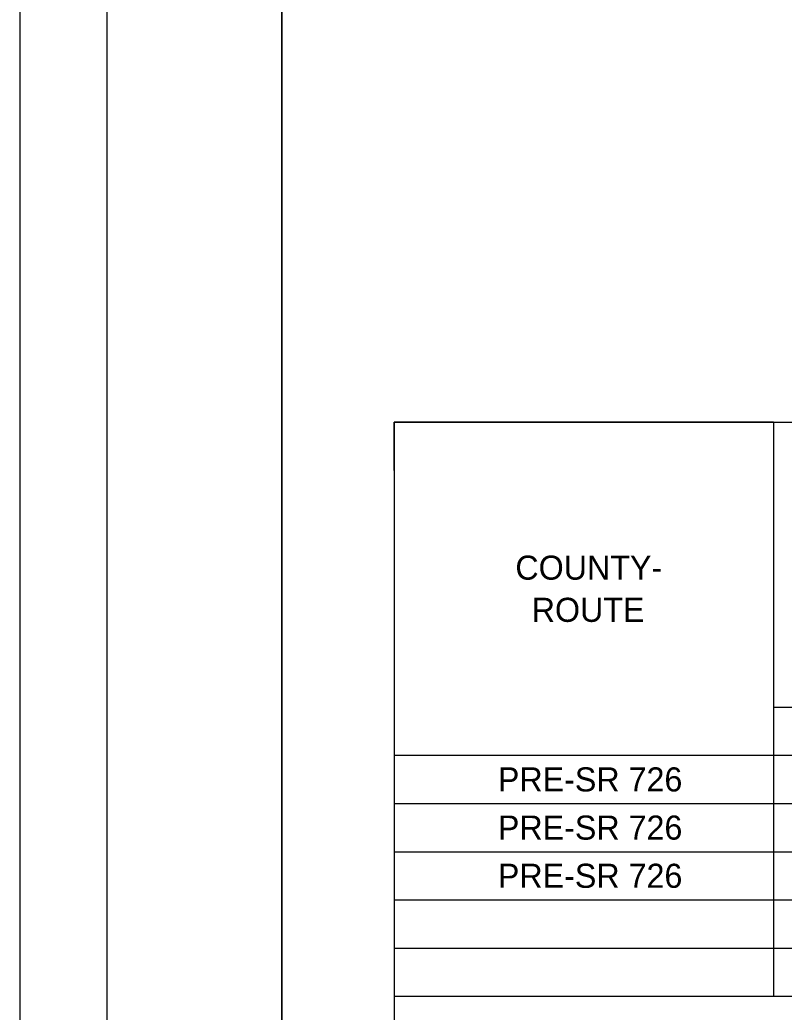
# Model space of a CAD drawing. Extents: x 0 to 34, y 0 to 22.
# Drawn here: x 0 to 4.38, y 3.42 to 9.11 of the extents above; entities that cross this region are included whole.
import ezdxf

# ---------------------------------------------------------------- set-up
doc = ezdxf.new("R2010")
doc.units = 0
for name, color, linetype in [('SH_Border', 7, 'Continuous'), ('SH_Cut_Line', 7, 'Continuous'), ('SH_Text', 7, 'Continuous')]:
    doc.layers.add(name, color=color, linetype=linetype)

msp = doc.modelspace()

# ---------------------------------------------------------------- linework, layer by layer
at = {"layer": 'SH_Border'}
for points in [[(0.5, 21.5), (1.5, 21.5), (1.5, 0.5), (0.5, 0.5)], [(1.5, 21.5), (33.5, 21.5), (33.5, 0.5), (1.5, 0.5)]]:
    msp.add_lwpolyline(points, close=True, dxfattribs=at)
at = {"layer": 'SH_Cut_Line'}
msp.add_lwpolyline([(0, 0), (34, 0), (34, 22), (0, 22)], close=True, dxfattribs=at)
at = {"layer": 'SH_Text'}
for p, q in [((2.1442, 6.801), (5.3482, 6.801)), ((2.1442, 6.801), (2.1442, 5.997)), ((4.3162, 6.801), (4.3162, 5.997)), ((2.1442, 5.997), (2.1442, 5.169)), ((4.3162, 5.997), (4.3162, 5.169)), ((2.1442, 5.169), (2.1442, 4.065)), ((4.3162, 5.169), (5.3482, 5.169)), ((4.3162, 5.169), (4.3162, 4.065)), ((2.1442, 4.893), (5.3482, 4.893)), ((2.1442, 4.617), (5.3482, 4.617)), ((2.1442, 4.341), (5.3482, 4.341)), ((2.1442, 4.065), (5.3482, 4.065)), ((2.1442, 4.065), (2.1442, 3.789)), ((4.3162, 4.065), (4.3162, 3.789)), ((2.1442, 3.789), (5.3482, 3.789)), ((2.1442, 3.789), (2.1442, 2.769)), ((4.3162, 3.789), (4.3162, 3.513)), ((2.1442, 3.513), (5.3482, 3.513))]:
    msp.add_line(p, q, dxfattribs=at)
for points in [[(2.1442, 6.801), (2.1442, 6.801), (2.1442, 6.525), (2.1442, 6.525)], [(2.1442, 6.801), (2.1442, 6.801), (2.1442, 6.525), (2.1442, 6.525)], [(2.1442, 6.801), (2.1442, 6.801), (2.1442, 6.801), (2.1442, 6.801)], [(2.1442, 6.801), (2.1442, 6.801), (2.1442, 6.801), (2.1442, 6.801)], [(2.1442, 6.801), (2.1442, 6.801), (2.1442, 6.801), (2.1442, 6.801)], [(2.1442, 6.801), (2.1442, 6.801), (2.1442, 6.801), (2.1442, 6.801)], [(2.1442, 6.801), (2.1442, 6.801), (2.1442, 6.801), (2.1442, 6.801)], [(2.1442, 6.801), (2.1442, 6.801), (2.1442, 6.801), (2.1442, 6.801)], [(2.1442, 6.801), (2.1442, 6.801), (2.1442, 6.801), (2.1442, 6.801)], [(2.1442, 6.801), (2.1442, 6.801), (2.1442, 6.801), (2.1442, 6.801)], [(2.1442, 6.801), (2.1442, 6.801), (2.1442, 6.801), (2.1442, 6.801)], [(2.1442, 6.801), (2.1442, 6.801), (2.1442, 6.525), (2.1442, 6.525)], [(2.1442, 6.801), (2.1442, 6.801), (2.1442, 6.525), (2.1442, 6.525)], [(2.1442, 6.801), (2.1442, 6.801), (2.1442, 6.525), (2.1442, 6.525)], [(2.1442, 6.801), (2.1442, 6.801), (2.1442, 6.525), (2.1442, 6.525)], [(2.1442, 6.801), (2.1442, 6.801), (2.1442, 6.525), (2.1442, 6.525)], [(2.1442, 6.801), (2.1442, 6.801), (2.1442, 6.525), (2.1442, 6.525)], [(2.1442, 6.801), (2.1442, 6.801), (2.1442, 6.525), (2.1442, 6.525)], [(2.1442, 6.801), (2.1442, 6.801), (2.1442, 6.525), (2.1442, 6.525)], [(2.1442, 6.801), (2.1442, 6.801), (2.1442, 6.525), (2.1442, 6.525)], [(2.1442, 6.801), (2.1442, 6.801), (2.1442, 6.525), (2.1442, 6.525)], [(2.1442, 6.801), (2.1442, 6.801), (2.1442, 6.525), (2.1442, 6.525)], [(2.1442, 6.801), (2.1442, 6.801), (2.1442, 6.525), (2.1442, 6.525)], [(2.1442, 6.801), (2.1442, 6.801), (2.1442, 6.525), (2.1442, 6.525)], [(2.1442, 6.801), (2.1442, 6.801), (2.1442, 6.525), (2.1442, 6.525)], [(2.1442, 6.801), (2.1442, 6.801), (2.1442, 6.525), (2.1442, 6.525)], [(2.1442, 6.801), (2.1442, 6.801), (2.1442, 6.525), (2.1442, 6.525)], [(2.1442, 6.801), (2.1442, 6.801), (2.1442, 6.525), (2.1442, 6.525)], [(2.1442, 6.801), (2.1442, 6.801), (2.1442, 6.525), (2.1442, 6.525)], [(2.1442, 6.801), (2.1442, 6.801), (2.1442, 6.525), (2.1442, 6.525)], [(2.1442, 6.801), (2.1442, 6.801), (2.1442, 6.525), (2.1442, 6.525)], [(2.1442, 6.801), (2.1442, 6.801), (2.1442, 6.525), (2.1442, 6.525)], [(2.1442, 6.801), (2.1442, 6.801), (2.1442, 6.525), (2.1442, 6.525)], [(2.1442, 6.801), (2.1442, 6.801), (2.1442, 6.525), (2.1442, 6.525)], [(2.1442, 6.801), (2.1442, 6.801), (2.1442, 6.525), (2.1442, 6.525)], [(2.1442, 6.801), (2.1442, 6.801), (2.1442, 6.525), (2.1442, 6.525)], [(2.1442, 6.801), (2.1442, 6.801), (2.1442, 6.525), (2.1442, 6.525)], [(2.1442, 6.801), (2.1442, 6.801), (2.1442, 6.525), (2.1442, 6.525)], [(2.1442, 6.801), (2.1442, 6.801), (2.1442, 6.525), (2.1442, 6.525)], [(2.1442, 6.801), (2.1442, 6.801), (2.1442, 6.525), (2.1442, 6.525)], [(2.1442, 6.801), (2.1442, 6.801), (2.1442, 6.525), (2.1442, 6.525)], [(2.1442, 6.801), (2.1442, 6.801), (2.1442, 6.525), (2.1442, 6.525)], [(2.1442, 6.801), (2.1442, 6.801), (2.1442, 6.525), (2.1442, 6.525)], [(2.1442, 6.801), (2.1442, 6.801), (2.1442, 6.525), (2.1442, 6.525)], [(2.1442, 6.801), (2.1442, 6.801), (2.1442, 6.525), (2.1442, 6.525)], [(2.1442, 6.801), (2.1442, 6.801), (2.1442, 6.525), (2.1442, 6.525)], [(2.1442, 6.801), (2.1442, 6.801), (2.1442, 6.525), (2.1442, 6.525)], [(2.1442, 6.801), (4.3162, 6.801), (4.3162, 6.801), (2.1442, 6.801)], [(2.1442, 6.801), (3.1762, 6.801), (3.1762, 6.801), (2.1442, 6.801)], [(2.1442, 6.801), (3.2962, 6.801), (3.2962, 6.801), (2.1442, 6.801)], [(2.1442, 6.801), (3.1762, 6.801), (3.1762, 6.801), (2.1442, 6.801)], [(2.1442, 6.801), (3.1882, 6.801), (3.1882, 6.801), (2.1442, 6.801)], [(2.1442, 6.801), (2.1442, 6.801), (2.1442, 6.801), (2.1442, 6.801)], [(2.1442, 6.801), (2.1442, 6.801), (2.1442, 6.801), (2.1442, 6.801)], [(2.1442, 6.801), (3.2362, 6.801), (3.2362, 6.801), (2.1442, 6.801)], [(2.1442, 6.801), (3.1042, 6.801), (3.1042, 6.801), (2.1442, 6.801)], [(2.1442, 6.801), (2.1442, 6.801), (2.1442, 6.801), (2.1442, 6.801)], [(2.1442, 6.801), (2.1442, 6.801), (2.1442, 6.801), (2.1442, 6.801)], [(2.1442, 6.801), (3.1042, 6.801), (3.1042, 6.801), (2.1442, 6.801)], [(2.1442, 6.801), (3.1042, 6.801), (3.1042, 6.801), (2.1442, 6.801)], [(2.1442, 6.801), (3.1042, 6.801), (3.1042, 6.801), (2.1442, 6.801)], [(2.1442, 6.801), (3.1042, 6.801), (3.1042, 6.801), (2.1442, 6.801)], [(2.1442, 6.801), (3.1042, 6.801), (3.1042, 6.801), (2.1442, 6.801)], [(2.1442, 6.801), (3.2602, 6.801), (3.2602, 6.801), (2.1442, 6.801)], [(2.1442, 6.801), (3.1282, 6.801), (3.1282, 6.801), (2.1442, 6.801)], [(2.1442, 6.801), (3.1282, 6.801), (3.1282, 6.801), (2.1442, 6.801)], [(2.1442, 6.801), (2.1442, 6.801), (2.1442, 6.801), (2.1442, 6.801)], [(2.1442, 6.801), (2.1442, 6.801), (2.1442, 6.801), (2.1442, 6.801)], [(2.1442, 6.801), (2.1442, 6.801), (2.1442, 6.801), (2.1442, 6.801)], [(2.1442, 6.801), (4.3162, 6.801), (4.3162, 6.801), (2.1442, 6.801)], [(2.1442, 6.801), (3.1762, 6.801), (3.1762, 6.801), (2.1442, 6.801)], [(2.1442, 6.801), (3.2962, 6.801), (3.2962, 6.801), (2.1442, 6.801)], [(2.1442, 6.801), (3.1762, 6.801), (3.1762, 6.801), (2.1442, 6.801)], [(2.1442, 6.801), (3.1882, 6.801), (3.1882, 6.801), (2.1442, 6.801)], [(2.1442, 6.801), (2.1442, 6.801), (2.1442, 6.801), (2.1442, 6.801)], [(2.1442, 6.801), (2.1442, 6.801), (2.1442, 6.801), (2.1442, 6.801)], [(2.1442, 6.801), (3.2362, 6.801), (3.2362, 6.801), (2.1442, 6.801)], [(2.1442, 6.801), (3.1042, 6.801), (3.1042, 6.801), (2.1442, 6.801)], [(2.1442, 6.801), (2.1442, 6.801), (2.1442, 6.801), (2.1442, 6.801)], [(2.1442, 6.801), (2.1442, 6.801), (2.1442, 6.801), (2.1442, 6.801)], [(2.1442, 6.801), (3.1042, 6.801), (3.1042, 6.801), (2.1442, 6.801)], [(2.1442, 6.801), (3.1042, 6.801), (3.1042, 6.801), (2.1442, 6.801)], [(2.1442, 6.801), (3.1042, 6.801), (3.1042, 6.801), (2.1442, 6.801)], [(2.1442, 6.801), (3.1042, 6.801), (3.1042, 6.801), (2.1442, 6.801)], [(2.1442, 6.801), (3.1042, 6.801), (3.1042, 6.801), (2.1442, 6.801)], [(2.1442, 6.801), (3.2602, 6.801), (3.2602, 6.801), (2.1442, 6.801)], [(2.1442, 6.801), (3.1282, 6.801), (3.1282, 6.801), (2.1442, 6.801)], [(2.1442, 6.801), (3.1282, 6.801), (3.1282, 6.801), (2.1442, 6.801)], [(2.1442, 6.801), (2.1442, 6.801), (2.1442, 6.801), (2.1442, 6.801)], [(2.1442, 6.801), (2.1442, 6.801), (2.1442, 6.801), (2.1442, 6.801)], [(2.1442, 6.801), (2.1442, 6.801), (2.1442, 6.801), (2.1442, 6.801)], [(2.1442, 6.801), (4.3162, 6.801), (4.3162, 6.801), (2.1442, 6.801)], [(2.1442, 6.801), (3.1762, 6.801), (3.1762, 6.801), (2.1442, 6.801)], [(2.1442, 6.801), (3.2962, 6.801), (3.2962, 6.801), (2.1442, 6.801)], [(2.1442, 6.801), (3.1762, 6.801), (3.1762, 6.801), (2.1442, 6.801)], [(2.1442, 6.801), (3.1882, 6.801), (3.1882, 6.801), (2.1442, 6.801)], [(2.1442, 6.801), (2.1442, 6.801), (2.1442, 6.801), (2.1442, 6.801)], [(2.1442, 6.801), (2.1442, 6.801), (2.1442, 6.801), (2.1442, 6.801)], [(2.1442, 6.801), (3.2362, 6.801), (3.2362, 6.801), (2.1442, 6.801)], [(2.1442, 6.801), (3.1042, 6.801), (3.1042, 6.801), (2.1442, 6.801)], [(2.1442, 6.801), (2.1442, 6.801), (2.1442, 6.801), (2.1442, 6.801)], [(2.1442, 6.801), (2.1442, 6.801), (2.1442, 6.801), (2.1442, 6.801)], [(2.1442, 6.801), (3.1042, 6.801), (3.1042, 6.801), (2.1442, 6.801)], [(2.1442, 6.801), (3.1042, 6.801), (3.1042, 6.801), (2.1442, 6.801)], [(2.1442, 6.801), (3.1042, 6.801), (3.1042, 6.801), (2.1442, 6.801)], [(2.1442, 6.801), (3.1042, 6.801), (3.1042, 6.801), (2.1442, 6.801)], [(2.1442, 6.801), (3.1042, 6.801), (3.1042, 6.801), (2.1442, 6.801)], [(2.1442, 6.801), (3.2602, 6.801), (3.2602, 6.801), (2.1442, 6.801)], [(2.1442, 6.801), (3.1282, 6.801), (3.1282, 6.801), (2.1442, 6.801)], [(2.1442, 6.801), (3.1282, 6.801), (3.1282, 6.801), (2.1442, 6.801)], [(2.1442, 6.801), (2.1442, 6.801), (2.1442, 6.801), (2.1442, 6.801)], [(2.1442, 6.801), (2.1442, 6.801), (2.1442, 6.801), (2.1442, 6.801)], [(2.1442, 6.801), (2.1442, 6.801), (2.1442, 6.801), (2.1442, 6.801)], [(2.1442, 6.801), (4.3162, 6.801), (4.3162, 6.801), (2.1442, 6.801)], [(2.1442, 6.801), (3.1762, 6.801), (3.1762, 6.801), (2.1442, 6.801)], [(2.1442, 6.801), (3.2962, 6.801), (3.2962, 6.801), (2.1442, 6.801)], [(2.1442, 6.801), (3.1762, 6.801), (3.1762, 6.801), (2.1442, 6.801)], [(2.1442, 6.801), (3.1882, 6.801), (3.1882, 6.801), (2.1442, 6.801)], [(2.1442, 6.801), (2.1442, 6.801), (2.1442, 6.801), (2.1442, 6.801)], [(2.1442, 6.801), (2.1442, 6.801), (2.1442, 6.801), (2.1442, 6.801)], [(2.1442, 6.801), (3.2362, 6.801), (3.2362, 6.801), (2.1442, 6.801)], [(2.1442, 6.801), (3.1042, 6.801), (3.1042, 6.801), (2.1442, 6.801)], [(2.1442, 6.801), (2.1442, 6.801), (2.1442, 6.801), (2.1442, 6.801)], [(2.1442, 6.801), (2.1442, 6.801), (2.1442, 6.801), (2.1442, 6.801)], [(2.1442, 6.801), (3.1042, 6.801), (3.1042, 6.801), (2.1442, 6.801)], [(2.1442, 6.801), (3.1042, 6.801), (3.1042, 6.801), (2.1442, 6.801)], [(2.1442, 6.801), (3.1042, 6.801), (3.1042, 6.801), (2.1442, 6.801)], [(2.1442, 6.801), (3.1042, 6.801), (3.1042, 6.801), (2.1442, 6.801)], [(2.1442, 6.801), (3.1042, 6.801), (3.1042, 6.801), (2.1442, 6.801)], [(2.1442, 6.801), (3.2602, 6.801), (3.2602, 6.801), (2.1442, 6.801)], [(2.1442, 6.801), (3.1282, 6.801), (3.1282, 6.801), (2.1442, 6.801)], [(2.1442, 6.801), (3.1282, 6.801), (3.1282, 6.801), (2.1442, 6.801)], [(2.1442, 6.801), (2.1442, 6.801), (2.1442, 6.801), (2.1442, 6.801)], [(2.1442, 6.801), (2.1442, 6.801), (2.1442, 6.801), (2.1442, 6.801)], [(2.1442, 6.801), (2.1442, 6.801), (2.1442, 6.801), (2.1442, 6.801)], [(2.1442, 6.801), (4.3162, 6.801), (4.3162, 6.801), (2.1442, 6.801)], [(2.1442, 6.801), (3.1762, 6.801), (3.1762, 6.801), (2.1442, 6.801)], [(2.1442, 6.801), (3.2962, 6.801), (3.2962, 6.801), (2.1442, 6.801)], [(2.1442, 6.801), (3.1762, 6.801), (3.1762, 6.801), (2.1442, 6.801)], [(2.1442, 6.801), (3.1882, 6.801), (3.1882, 6.801), (2.1442, 6.801)], [(2.1442, 6.801), (2.1442, 6.801), (2.1442, 6.801), (2.1442, 6.801)], [(2.1442, 6.801), (2.1442, 6.801), (2.1442, 6.801), (2.1442, 6.801)], [(2.1442, 6.801), (3.2362, 6.801), (3.2362, 6.801), (2.1442, 6.801)], [(2.1442, 6.801), (3.1042, 6.801), (3.1042, 6.801), (2.1442, 6.801)], [(2.1442, 6.801), (2.1442, 6.801), (2.1442, 6.801), (2.1442, 6.801)], [(2.1442, 6.801), (2.1442, 6.801), (2.1442, 6.801), (2.1442, 6.801)], [(2.1442, 6.801), (3.1042, 6.801), (3.1042, 6.801), (2.1442, 6.801)], [(2.1442, 6.801), (3.1042, 6.801), (3.1042, 6.801), (2.1442, 6.801)], [(2.1442, 6.801), (3.1042, 6.801), (3.1042, 6.801), (2.1442, 6.801)], [(2.1442, 6.801), (3.1042, 6.801), (3.1042, 6.801), (2.1442, 6.801)], [(2.1442, 6.801), (3.1042, 6.801), (3.1042, 6.801), (2.1442, 6.801)], [(2.1442, 6.801), (3.2602, 6.801), (3.2602, 6.801), (2.1442, 6.801)], [(2.1442, 6.801), (3.1282, 6.801), (3.1282, 6.801), (2.1442, 6.801)], [(2.1442, 6.801), (3.1282, 6.801), (3.1282, 6.801), (2.1442, 6.801)], [(2.1442, 6.801), (2.1442, 6.801), (2.1442, 6.801), (2.1442, 6.801)], [(2.1442, 6.801), (2.1442, 6.801), (2.1442, 6.801), (2.1442, 6.801)], [(2.1442, 6.801), (2.1442, 6.801), (2.1442, 6.801), (2.1442, 6.801)], [(2.1442, 6.801), (4.3162, 6.801), (4.3162, 6.801), (2.1442, 6.801)], [(2.1442, 6.801), (3.1762, 6.801), (3.1762, 6.801), (2.1442, 6.801)], [(2.1442, 6.801), (3.2962, 6.801), (3.2962, 6.801), (2.1442, 6.801)], [(2.1442, 6.801), (3.1762, 6.801), (3.1762, 6.801), (2.1442, 6.801)], [(2.1442, 6.801), (3.1882, 6.801), (3.1882, 6.801), (2.1442, 6.801)], [(2.1442, 6.801), (2.1442, 6.801), (2.1442, 6.801), (2.1442, 6.801)], [(2.1442, 6.801), (2.1442, 6.801), (2.1442, 6.801), (2.1442, 6.801)], [(2.1442, 6.801), (3.2362, 6.801), (3.2362, 6.801), (2.1442, 6.801)], [(2.1442, 6.801), (3.1042, 6.801), (3.1042, 6.801), (2.1442, 6.801)], [(2.1442, 6.801), (2.1442, 6.801), (2.1442, 6.801), (2.1442, 6.801)], [(2.1442, 6.801), (2.1442, 6.801), (2.1442, 6.801), (2.1442, 6.801)], [(2.1442, 6.801), (3.1042, 6.801), (3.1042, 6.801), (2.1442, 6.801)], [(2.1442, 6.801), (3.1042, 6.801), (3.1042, 6.801), (2.1442, 6.801)], [(2.1442, 6.801), (3.1042, 6.801), (3.1042, 6.801), (2.1442, 6.801)], [(2.1442, 6.801), (3.1042, 6.801), (3.1042, 6.801), (2.1442, 6.801)], [(2.1442, 6.801), (3.1042, 6.801), (3.1042, 6.801), (2.1442, 6.801)], [(2.1442, 6.801), (3.2602, 6.801), (3.2602, 6.801), (2.1442, 6.801)], [(2.1442, 6.801), (3.1282, 6.801), (3.1282, 6.801), (2.1442, 6.801)], [(2.1442, 6.801), (3.1282, 6.801), (3.1282, 6.801), (2.1442, 6.801)], [(2.1442, 6.801), (2.1442, 6.801), (2.1442, 6.801), (2.1442, 6.801)], [(2.1442, 6.801), (2.1442, 6.801), (2.1442, 6.801), (2.1442, 6.801)], [(2.1442, 6.801), (2.1442, 6.801), (2.1442, 6.801), (2.1442, 6.801)], [(2.1442, 6.801), (4.3162, 6.801), (4.3162, 6.801), (2.1442, 6.801)], [(2.1442, 6.801), (3.1762, 6.801), (3.1762, 6.801), (2.1442, 6.801)], [(2.1442, 6.801), (3.2962, 6.801), (3.2962, 6.801), (2.1442, 6.801)], [(2.1442, 6.801), (3.1762, 6.801), (3.1762, 6.801), (2.1442, 6.801)], [(2.1442, 6.801), (3.1882, 6.801), (3.1882, 6.801), (2.1442, 6.801)], [(2.1442, 6.801), (2.1442, 6.801), (2.1442, 6.801), (2.1442, 6.801)], [(2.1442, 6.801), (2.1442, 6.801), (2.1442, 6.801), (2.1442, 6.801)], [(2.1442, 6.801), (3.2362, 6.801), (3.2362, 6.801), (2.1442, 6.801)], [(2.1442, 6.801), (3.1042, 6.801), (3.1042, 6.801), (2.1442, 6.801)], [(2.1442, 6.801), (2.1442, 6.801), (2.1442, 6.801), (2.1442, 6.801)], [(2.1442, 6.801), (2.1442, 6.801), (2.1442, 6.801), (2.1442, 6.801)], [(2.1442, 6.801), (3.1042, 6.801), (3.1042, 6.801), (2.1442, 6.801)], [(2.1442, 6.801), (3.1042, 6.801), (3.1042, 6.801), (2.1442, 6.801)], [(2.1442, 6.801), (3.1042, 6.801), (3.1042, 6.801), (2.1442, 6.801)], [(2.1442, 6.801), (3.1042, 6.801), (3.1042, 6.801), (2.1442, 6.801)], [(2.1442, 6.801), (3.1042, 6.801), (3.1042, 6.801), (2.1442, 6.801)], [(2.1442, 6.801), (3.2602, 6.801), (3.2602, 6.801), (2.1442, 6.801)], [(2.1442, 6.801), (3.1282, 6.801), (3.1282, 6.801), (2.1442, 6.801)], [(2.1442, 6.801), (3.1282, 6.801), (3.1282, 6.801), (2.1442, 6.801)], [(2.1442, 6.801), (2.1442, 6.801), (2.1442, 6.801), (2.1442, 6.801)], [(2.1442, 6.801), (2.1442, 6.801), (2.1442, 6.801), (2.1442, 6.801)], [(2.1442, 6.801), (2.1442, 6.801), (2.1442, 6.801), (2.1442, 6.801)], [(2.1442, 6.801), (4.3162, 6.801), (4.3162, 6.801), (2.1442, 6.801)], [(2.1442, 6.801), (3.1762, 6.801), (3.1762, 6.801), (2.1442, 6.801)], [(2.1442, 6.801), (3.2962, 6.801), (3.2962, 6.801), (2.1442, 6.801)], [(2.1442, 6.801), (3.1762, 6.801), (3.1762, 6.801), (2.1442, 6.801)], [(2.1442, 6.801), (3.1882, 6.801), (3.1882, 6.801), (2.1442, 6.801)], [(2.1442, 6.801), (2.1442, 6.801), (2.1442, 6.801), (2.1442, 6.801)], [(2.1442, 6.801), (2.1442, 6.801), (2.1442, 6.801), (2.1442, 6.801)], [(2.1442, 6.801), (3.2362, 6.801), (3.2362, 6.801), (2.1442, 6.801)], [(2.1442, 6.801), (3.1042, 6.801), (3.1042, 6.801), (2.1442, 6.801)], [(2.1442, 6.801), (2.1442, 6.801), (2.1442, 6.801), (2.1442, 6.801)], [(2.1442, 6.801), (2.1442, 6.801), (2.1442, 6.801), (2.1442, 6.801)], [(2.1442, 6.801), (3.1042, 6.801), (3.1042, 6.801), (2.1442, 6.801)], [(2.1442, 6.801), (3.1042, 6.801), (3.1042, 6.801), (2.1442, 6.801)], [(2.1442, 6.801), (3.1042, 6.801), (3.1042, 6.801), (2.1442, 6.801)], [(2.1442, 6.801), (3.1042, 6.801), (3.1042, 6.801), (2.1442, 6.801)], [(2.1442, 6.801), (3.1042, 6.801), (3.1042, 6.801), (2.1442, 6.801)], [(2.1442, 6.801), (3.2602, 6.801), (3.2602, 6.801), (2.1442, 6.801)], [(2.1442, 6.801), (3.1282, 6.801), (3.1282, 6.801), (2.1442, 6.801)], [(2.1442, 6.801), (3.1282, 6.801), (3.1282, 6.801), (2.1442, 6.801)], [(2.1442, 6.801), (2.1442, 6.801), (2.1442, 6.801), (2.1442, 6.801)], [(2.1442, 6.801), (2.1442, 6.801), (2.1442, 6.801), (2.1442, 6.801)], [(2.1442, 6.801), (2.1442, 6.801), (2.1442, 6.801), (2.1442, 6.801)], [(2.1442, 6.801), (4.3162, 6.801), (4.3162, 6.801), (2.1442, 6.801)], [(2.1442, 6.801), (3.1762, 6.801), (3.1762, 6.801), (2.1442, 6.801)], [(2.1442, 6.801), (3.2962, 6.801), (3.2962, 6.801), (2.1442, 6.801)], [(2.1442, 6.801), (3.1762, 6.801), (3.1762, 6.801), (2.1442, 6.801)], [(2.1442, 6.801), (3.1882, 6.801), (3.1882, 6.801), (2.1442, 6.801)], [(2.1442, 6.801), (2.1442, 6.801), (2.1442, 6.801), (2.1442, 6.801)], [(2.1442, 6.801), (2.1442, 6.801), (2.1442, 6.801), (2.1442, 6.801)], [(2.1442, 6.801), (3.2362, 6.801), (3.2362, 6.801), (2.1442, 6.801)], [(2.1442, 6.801), (3.1042, 6.801), (3.1042, 6.801), (2.1442, 6.801)], [(2.1442, 6.801), (2.1442, 6.801), (2.1442, 6.801), (2.1442, 6.801)], [(2.1442, 6.801), (2.1442, 6.801), (2.1442, 6.801), (2.1442, 6.801)], [(2.1442, 6.801), (3.1042, 6.801), (3.1042, 6.801), (2.1442, 6.801)], [(2.1442, 6.801), (3.1042, 6.801), (3.1042, 6.801), (2.1442, 6.801)], [(2.1442, 6.801), (3.1042, 6.801), (3.1042, 6.801), (2.1442, 6.801)], [(2.1442, 6.801), (3.1042, 6.801), (3.1042, 6.801), (2.1442, 6.801)], [(2.1442, 6.801), (3.1042, 6.801), (3.1042, 6.801), (2.1442, 6.801)], [(2.1442, 6.801), (3.2602, 6.801), (3.2602, 6.801), (2.1442, 6.801)], [(2.1442, 6.801), (3.1282, 6.801), (3.1282, 6.801), (2.1442, 6.801)], [(2.1442, 6.801), (3.1282, 6.801), (3.1282, 6.801), (2.1442, 6.801)], [(2.1442, 6.801), (2.1442, 6.801), (2.1442, 6.801), (2.1442, 6.801)], [(2.1442, 6.801), (2.1442, 6.801), (2.1442, 6.801), (2.1442, 6.801)], [(2.1442, 6.801), (2.1442, 6.801), (2.1442, 6.801), (2.1442, 6.801)], [(2.1442, 6.801), (4.3162, 6.801), (4.3162, 6.801), (2.1442, 6.801)], [(2.1442, 6.801), (3.1762, 6.801), (3.1762, 6.801), (2.1442, 6.801)], [(2.1442, 6.801), (3.2962, 6.801), (3.2962, 6.801), (2.1442, 6.801)], [(2.1442, 6.801), (3.1762, 6.801), (3.1762, 6.801), (2.1442, 6.801)], [(2.1442, 6.801), (3.1882, 6.801), (3.1882, 6.801), (2.1442, 6.801)], [(2.1442, 6.801), (2.1442, 6.801), (2.1442, 6.801), (2.1442, 6.801)], [(2.1442, 6.801), (2.1442, 6.801), (2.1442, 6.801), (2.1442, 6.801)], [(2.1442, 6.801), (3.2362, 6.801), (3.2362, 6.801), (2.1442, 6.801)], [(2.1442, 6.801), (3.1042, 6.801), (3.1042, 6.801), (2.1442, 6.801)], [(2.1442, 6.801), (2.1442, 6.801), (2.1442, 6.801), (2.1442, 6.801)], [(2.1442, 6.801), (2.1442, 6.801), (2.1442, 6.801), (2.1442, 6.801)], [(2.1442, 6.801), (3.1042, 6.801), (3.1042, 6.801), (2.1442, 6.801)], [(2.1442, 6.801), (3.1042, 6.801), (3.1042, 6.801), (2.1442, 6.801)], [(2.1442, 6.801), (3.1042, 6.801), (3.1042, 6.801), (2.1442, 6.801)], [(2.1442, 6.801), (3.1042, 6.801), (3.1042, 6.801), (2.1442, 6.801)], [(2.1442, 6.801), (3.1042, 6.801), (3.1042, 6.801), (2.1442, 6.801)], [(2.1442, 6.801), (3.2602, 6.801), (3.2602, 6.801), (2.1442, 6.801)], [(2.1442, 6.801), (3.1282, 6.801), (3.1282, 6.801), (2.1442, 6.801)], [(2.1442, 6.801), (3.1282, 6.801), (3.1282, 6.801), (2.1442, 6.801)], [(2.1442, 6.801), (2.1442, 6.801), (2.1442, 6.801), (2.1442, 6.801)], [(2.1442, 6.801), (2.1442, 6.801), (2.1442, 6.801), (2.1442, 6.801)], [(2.1442, 6.801), (2.1442, 6.801), (2.1442, 6.801), (2.1442, 6.801)], [(2.1442, 6.801), (2.1442, 6.801), (2.1442, 6.801), (2.1442, 6.801)], [(2.1442, 6.801), (2.1442, 6.801), (2.1442, 6.801), (2.1442, 6.801)], [(2.1442, 6.801), (2.1442, 6.801), (2.1442, 6.801), (2.1442, 6.801)]]:
    msp.add_lwpolyline(points, close=True, dxfattribs=at)

# ---------------------------------------------------------------- texts
for s, p in [('COUNTY-', (2.8376, 5.8987)), ('ROUTE', (2.9311, 5.6572)), ('PRE-SR 726', (2.7374, 4.686)), ('PRE-SR 726', (2.7374, 4.41)), ('PRE-SR 726', (2.7374, 4.134))]:
    msp.add_text(s, height=0.138, dxfattribs=at).set_placement(p)

doc.saveas('drawing.dxf')
